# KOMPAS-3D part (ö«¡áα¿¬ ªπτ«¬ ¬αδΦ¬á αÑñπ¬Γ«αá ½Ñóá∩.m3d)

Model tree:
1. Эскиз:1
2. Операция выдавливания:2
     Расстояние 1 = 19
3. Эскиз:3
4. Вырезать элемент выдавливания:1
     Расстояние 1 = 1
5. Эскиз:4
6. Вырезать элемент выдавливания:2
     Расстояние 1 = 1
7. Эскиз:5
8. Вырезать элемент выдавливания:3
     Расстояние 1 = 1
9. Эскиз:6
10. Вырезать элемент выдавливания:4
     Расстояние 1 = 1
11. Эскиз:7
12. Вырезать элемент выдавливания:5
     Расстояние 1 = 13
13. Эскиз:8
14. Вырезать элемент выдавливания:6
     Расстояние 1 = 17
15. Эскиз:9
16. Вырезать элемент выдавливания:7
     Расстояние 1 = 17
17. Эскиз:10
18. Вырезать элемент выдавливания:8
     Расстояние 1 = 17
19. Эскиз:11
20. Вырезать элемент выдавливания:9
     Расстояние 1 = 16
21. Эскиз:12
22. Операция выдавливания:3
     Расстояние 1 = 6
23. Фаска:2
     Угол = 45; Длина 1 = 0.5; Длина 2 = 0.5
24. Фаска:3
     Угол = 45; Длина 1 = 0.5; Длина 2 = 0.5
25. Зеркальный массив:2  (with: Операция выдавливания:2, Вырезать элемент выдавливания:1, Вырезать элемент выдавливания:2, Вырезать элемент выдавливания:3, Вырезать элемент выдавливания:4, Вырезать элемент выдавливания:5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)  (labels: Экземпляр ( 1 ); Экземпляр ( 2 ))
26. Зеркальный массив:3  (with: Зеркальный массив:2, Операция выдавливания:2, Вырезать элемент выдавливания:1, Вырезать элемент выдавливания:2, Вырезать элемент выдавливания:3, Вырезать элемент выдавливания:4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)  (labels: Экземпляр ( 1 ); Экземпляр ( 2 ))
27. Фаска:4
     Угол = 45; Длина 1 = 0.5; Длина 2 = 0.5
28. Фаска:5
     Угол = 45; Длина 1 = 0.7; Длина 2 = 0.7
29. Фаска:6
     Угол = 45; Длина 1 = 0.8; Длина 2 = 0.8

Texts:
  Экземпляр ( 1 )
  Экземпляр ( 2 )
